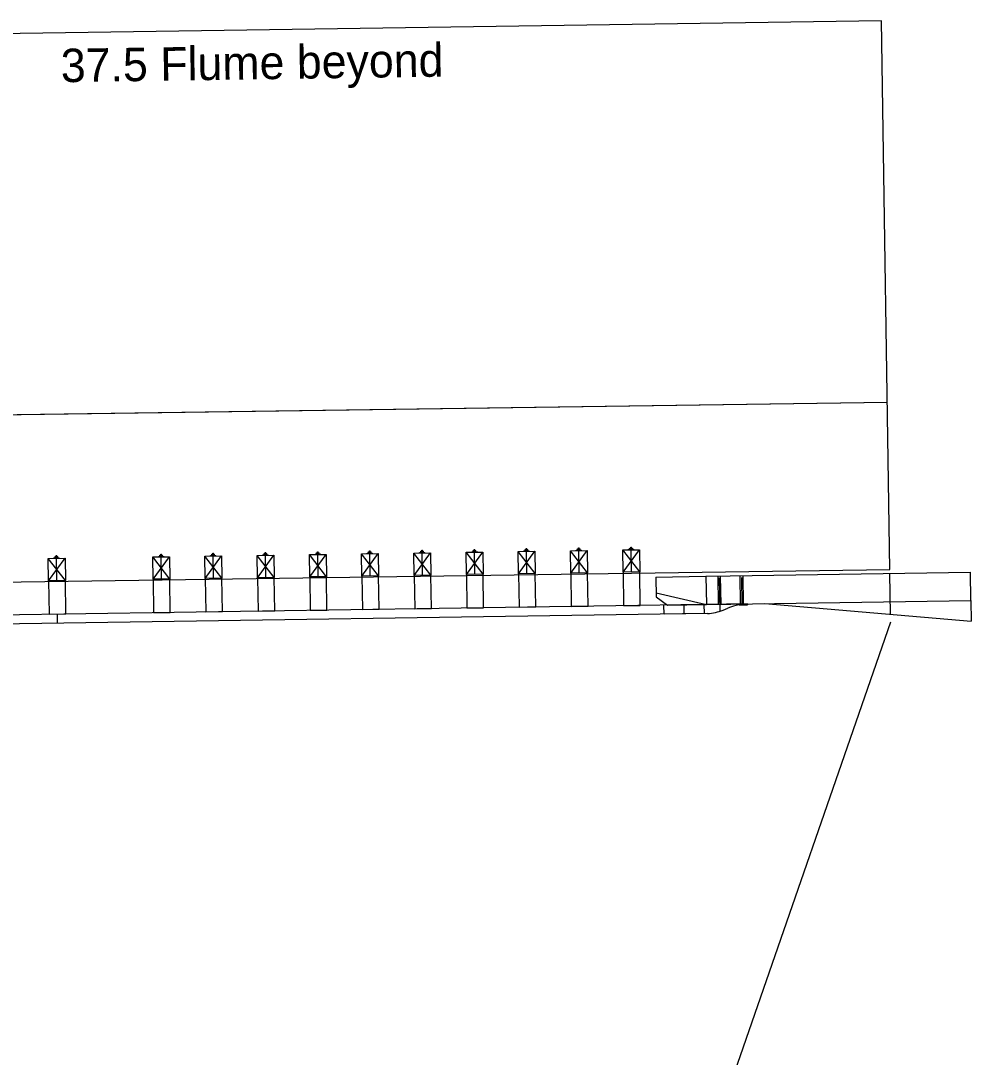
# Model space of a CAD drawing. Extents: x 17498307 to 17498862, y 7167523 to 7167641.
# Drawn here: x 17498465.8 to 17498494.24, y 7167590.21 to 7167621.22 of the extents above; entities that cross this region are included whole.
import ezdxf

# ---------------------------------------------------------------- set-up
doc = ezdxf.new("R2010")
doc.units = 0
for name, color, linetype in [('_CIVIL_CONSTRUCTION', 7, 'Continuous'), ('BridgeSuperStructure', 7, 'Continuous'), ('Draft_DNC', 7, 'Continuous'), ('dsnCellElements', 7, 'Continuous'), ('TL_ForeSlopeBarnRoof', 7, 'Continuous')]:
    doc.layers.add(name, color=color, linetype=linetype)

msp = doc.modelspace()

# ---------------------------------------------------------------- linework, layer by layer
at = {"layer": '_CIVIL_CONSTRUCTION'}
for p, q in [((17498432.532, 7167603.967), (17498491.798, 7167604.808)), ((17498491.825, 7167603.225), (17498476.465, 7167558.992))]:
    msp.add_line(p, q, dxfattribs=at)
at = {"layer": 'BridgeSuperStructure'}
msp.add_line((17498494.238, 7167603.261), (17498494.237, 7167603.261), dxfattribs=at)
at = {"layer": 'Draft_DNC'}
for p, q in [((17498491.553, 7167621.223), (17498454.056, 7167620.664)), ((17498491.798, 7167604.808), (17498491.553, 7167621.223)), ((17498432.461, 7167608.967), (17498491.727, 7167609.807))]:
    msp.add_line(p, q, dxfattribs=at)
at = {"layer": 'dsnCellElements'}
for p, q in [((17498474.674, 7167605.306), (17498474.674, 7167605.335)), ((17498474.674, 7167605.335), (17498474.694, 7167605.335)), ((17498474.694, 7167605.306), (17498474.694, 7167605.335)), ((17498476.236, 7167605.358), (17498476.256, 7167605.359)), ((17498476.237, 7167605.329), (17498476.236, 7167605.358)), ((17498476.257, 7167605.329), (17498476.256, 7167605.359)), ((17498477.769, 7167605.352), (17498477.849, 7167605.353)), ((17498477.769, 7167605.315), (17498477.769, 7167605.352)), ((17498477.785, 7167605.315), (17498477.785, 7167605.352)), ((17498477.799, 7167605.352), (17498477.798, 7167605.382)), ((17498477.798, 7167605.382), (17498477.818, 7167605.382)), ((17498477.819, 7167605.353), (17498477.818, 7167605.382)), ((17498477.833, 7167605.315), (17498477.833, 7167605.353)), ((17498477.849, 7167605.316), (17498477.849, 7167605.353)), ((17498479.292, 7167605.337), (17498479.452, 7167605.34)), ((17498479.292, 7167605.321), (17498479.292, 7167605.337)), ((17498479.331, 7167605.375), (17498479.411, 7167605.376)), ((17498479.332, 7167605.338), (17498479.331, 7167605.375)), ((17498479.348, 7167605.338), (17498479.347, 7167605.375)), ((17498479.361, 7167605.376), (17498479.361, 7167605.405)), ((17498479.361, 7167605.405), (17498479.381, 7167605.405)), ((17498479.381, 7167605.376), (17498479.381, 7167605.405)), ((17498479.396, 7167605.339), (17498479.395, 7167605.376)), ((17498479.412, 7167605.339), (17498479.411, 7167605.376)), ((17498479.452, 7167605.323), (17498479.452, 7167605.34)), ((17498480.684, 7167605.341), (17498481.184, 7167605.349)), ((17498481.194, 7167604.682), (17498480.684, 7167605.341)), ((17498480.694, 7167604.675), (17498481.184, 7167605.349)), ((17498480.854, 7167605.361), (17498481.014, 7167605.363)), ((17498480.854, 7167605.344), (17498480.854, 7167605.361)), ((17498480.893, 7167605.399), (17498480.973, 7167605.4)), ((17498480.894, 7167605.361), (17498480.893, 7167605.399)), ((17498480.91, 7167605.361), (17498480.909, 7167605.399)), ((17498480.923, 7167605.428), (17498480.943, 7167605.429)), ((17498480.923, 7167605.399), (17498480.923, 7167605.428)), ((17498480.944, 7167604.679), (17498480.934, 7167605.345)), ((17498480.943, 7167605.399), (17498480.943, 7167605.429)), ((17498480.958, 7167605.362), (17498480.957, 7167605.4)), ((17498480.974, 7167605.362), (17498480.973, 7167605.4)), ((17498481.014, 7167605.346), (17498481.014, 7167605.363)), ((17498482.247, 7167605.365), (17498482.747, 7167605.372)), ((17498482.757, 7167604.706), (17498482.247, 7167605.365)), ((17498482.257, 7167604.698), (17498482.747, 7167605.372)), ((17498482.416, 7167605.384), (17498482.576, 7167605.386)), ((17498482.417, 7167605.367), (17498482.416, 7167605.384)), ((17498482.456, 7167605.422), (17498482.536, 7167605.423)), ((17498482.456, 7167605.384), (17498482.456, 7167605.422)), ((17498482.472, 7167605.385), (17498482.472, 7167605.422)), ((17498482.486, 7167605.422), (17498482.485, 7167605.452)), ((17498482.485, 7167605.452), (17498482.505, 7167605.452)), ((17498482.507, 7167604.702), (17498482.497, 7167605.369)), ((17498482.506, 7167605.423), (17498482.505, 7167605.452)), ((17498482.52, 7167605.385), (17498482.52, 7167605.423)), ((17498482.536, 7167605.386), (17498482.536, 7167605.423)), ((17498482.577, 7167605.37), (17498482.576, 7167605.386)), ((17498483.809, 7167605.388), (17498484.309, 7167605.396)), ((17498484.319, 7167604.729), (17498483.809, 7167605.388)), ((17498483.819, 7167604.722), (17498484.309, 7167605.396)), ((17498483.979, 7167605.407), (17498484.139, 7167605.41)), ((17498483.979, 7167605.391), (17498483.979, 7167605.407)), ((17498484.018, 7167605.445), (17498484.098, 7167605.446)), ((17498484.019, 7167605.408), (17498484.018, 7167605.445)), ((17498484.035, 7167605.408), (17498484.034, 7167605.445)), ((17498484.048, 7167605.446), (17498484.048, 7167605.475)), ((17498484.048, 7167605.475), (17498484.068, 7167605.475)), ((17498484.069, 7167604.725), (17498484.059, 7167605.392)), ((17498484.068, 7167605.446), (17498484.068, 7167605.475)), ((17498484.083, 7167605.409), (17498484.082, 7167605.446)), ((17498484.099, 7167605.409), (17498484.098, 7167605.446)), ((17498484.139, 7167605.393), (17498484.139, 7167605.41)), ((17498466.623, 7167605.132), (17498467.123, 7167605.139)), ((17498467.133, 7167604.473), (17498466.623, 7167605.132)), ((17498466.633, 7167604.465), (17498467.123, 7167605.139)), ((17498466.793, 7167605.151), (17498466.953, 7167605.153)), ((17498466.793, 7167605.134), (17498466.793, 7167605.151)), ((17498466.833, 7167605.189), (17498466.913, 7167605.19)), ((17498466.833, 7167605.151), (17498466.833, 7167605.189)), ((17498466.849, 7167605.151), (17498466.849, 7167605.189)), ((17498466.863, 7167605.189), (17498466.862, 7167605.219)), ((17498466.862, 7167605.219), (17498466.882, 7167605.219)), ((17498466.883, 7167604.469), (17498466.873, 7167605.135)), ((17498466.883, 7167605.189), (17498466.882, 7167605.219)), ((17498466.897, 7167605.152), (17498466.897, 7167605.19)), ((17498466.913, 7167605.152), (17498466.913, 7167605.19)), ((17498466.953, 7167605.137), (17498466.953, 7167605.153)), ((17498469.748, 7167605.178), (17498470.248, 7167605.186)), ((17498470.258, 7167604.519), (17498469.748, 7167605.178)), ((17498469.758, 7167604.512), (17498470.248, 7167605.186)), ((17498469.918, 7167605.197), (17498470.078, 7167605.2)), ((17498469.918, 7167605.181), (17498469.918, 7167605.197)), ((17498469.957, 7167605.235), (17498470.037, 7167605.236)), ((17498469.958, 7167605.198), (17498469.957, 7167605.235)), ((17498469.974, 7167605.198), (17498469.973, 7167605.236)), ((17498469.987, 7167605.236), (17498469.987, 7167605.265)), ((17498469.987, 7167605.265), (17498470.007, 7167605.265)), ((17498470.008, 7167604.515), (17498469.998, 7167605.182)), ((17498470.007, 7167605.236), (17498470.007, 7167605.265)), ((17498470.022, 7167605.199), (17498470.021, 7167605.236)), ((17498470.038, 7167605.199), (17498470.037, 7167605.236)), ((17498470.078, 7167605.183), (17498470.078, 7167605.2)), ((17498471.31, 7167605.202), (17498471.81, 7167605.209)), ((17498471.82, 7167604.542), (17498471.31, 7167605.202)), ((17498471.32, 7167604.535), (17498471.81, 7167605.209)), ((17498471.48, 7167605.221), (17498471.64, 7167605.223)), ((17498471.48, 7167605.204), (17498471.48, 7167605.221)), ((17498471.52, 7167605.259), (17498471.6, 7167605.26)), ((17498471.52, 7167605.221), (17498471.52, 7167605.259)), ((17498471.536, 7167605.221), (17498471.536, 7167605.259)), ((17498471.55, 7167605.259), (17498471.549, 7167605.289)), ((17498471.549, 7167605.289), (17498471.569, 7167605.289)), ((17498471.57, 7167604.539), (17498471.56, 7167605.205)), ((17498471.57, 7167605.259), (17498471.569, 7167605.289)), ((17498471.584, 7167605.222), (17498471.584, 7167605.26)), ((17498471.6, 7167605.222), (17498471.6, 7167605.26)), ((17498471.64, 7167605.206), (17498471.64, 7167605.223)), ((17498472.873, 7167605.225), (17498473.373, 7167605.232)), ((17498473.383, 7167604.566), (17498472.873, 7167605.225)), ((17498472.883, 7167604.558), (17498473.373, 7167605.232)), ((17498473.042, 7167605.244), (17498473.202, 7167605.246)), ((17498473.043, 7167605.227), (17498473.042, 7167605.244)), ((17498473.082, 7167605.282), (17498473.162, 7167605.283)), ((17498473.082, 7167605.245), (17498473.082, 7167605.282)), ((17498473.098, 7167605.245), (17498473.098, 7167605.282)), ((17498473.112, 7167605.282), (17498473.111, 7167605.312)), ((17498473.111, 7167605.312), (17498473.131, 7167605.312)), ((17498473.133, 7167604.562), (17498473.123, 7167605.229)), ((17498473.132, 7167605.283), (17498473.131, 7167605.312)), ((17498473.146, 7167605.246), (17498473.146, 7167605.283)), ((17498473.162, 7167605.246), (17498473.162, 7167605.283)), ((17498473.203, 7167605.23), (17498473.202, 7167605.246)), ((17498474.435, 7167605.248), (17498474.935, 7167605.256)), ((17498474.945, 7167604.589), (17498474.435, 7167605.248)), ((17498474.445, 7167604.582), (17498474.935, 7167605.256)), ((17498474.605, 7167605.267), (17498474.765, 7167605.27)), ((17498474.605, 7167605.251), (17498474.605, 7167605.267)), ((17498474.644, 7167605.305), (17498474.724, 7167605.306)), ((17498474.645, 7167605.268), (17498474.644, 7167605.305)), ((17498474.661, 7167605.268), (17498474.66, 7167605.306)), ((17498474.695, 7167604.585), (17498474.685, 7167605.252)), ((17498474.709, 7167605.269), (17498474.708, 7167605.306)), ((17498474.725, 7167605.269), (17498474.724, 7167605.306)), ((17498474.765, 7167605.253), (17498474.765, 7167605.27)), ((17498475.997, 7167605.272), (17498476.497, 7167605.279)), ((17498476.507, 7167604.612), (17498475.997, 7167605.272)), ((17498476.007, 7167604.605), (17498476.497, 7167605.279)), ((17498476.167, 7167605.291), (17498476.327, 7167605.293)), ((17498476.167, 7167605.274), (17498476.167, 7167605.291)), ((17498476.207, 7167605.329), (17498476.287, 7167605.33)), ((17498476.207, 7167605.291), (17498476.207, 7167605.329)), ((17498476.223, 7167605.291), (17498476.223, 7167605.329)), ((17498476.257, 7167604.609), (17498476.247, 7167605.275)), ((17498476.271, 7167605.292), (17498476.271, 7167605.33)), ((17498476.287, 7167605.292), (17498476.287, 7167605.33)), ((17498476.327, 7167605.276), (17498476.327, 7167605.293)), ((17498477.56, 7167605.295), (17498478.06, 7167605.302)), ((17498478.07, 7167604.636), (17498477.56, 7167605.295)), ((17498477.57, 7167604.628), (17498478.06, 7167605.302)), ((17498477.729, 7167605.314), (17498477.889, 7167605.316)), ((17498477.73, 7167605.297), (17498477.729, 7167605.314)), ((17498477.82, 7167604.632), (17498477.81, 7167605.299)), ((17498477.89, 7167605.3), (17498477.889, 7167605.316)), ((17498479.122, 7167605.318), (17498479.622, 7167605.326)), ((17498479.632, 7167604.659), (17498479.122, 7167605.318)), ((17498479.132, 7167604.652), (17498479.622, 7167605.326)), ((17498479.382, 7167604.655), (17498479.372, 7167605.322)), ((17498484.319, 7167604.729), (17498483.819, 7167604.722)), ((17498483.819, 7167604.722), (17498483.834, 7167603.722)), ((17498484.334, 7167603.73), (17498484.319, 7167604.729)), ((17498487.029, 7167604.612), (17498494.216, 7167604.719)), ((17498494.229, 7167603.875), (17498494.216, 7167604.719)), ((17498467.133, 7167604.473), (17498466.633, 7167604.465)), ((17498466.633, 7167604.465), (17498466.648, 7167603.466)), ((17498467.148, 7167603.473), (17498467.133, 7167604.473)), ((17498470.258, 7167604.519), (17498469.758, 7167604.512)), ((17498469.758, 7167604.512), (17498469.773, 7167603.512)), ((17498470.273, 7167603.52), (17498470.258, 7167604.519)), ((17498471.82, 7167604.542), (17498471.32, 7167604.535)), ((17498471.32, 7167604.535), (17498471.335, 7167603.536)), ((17498471.835, 7167603.543), (17498471.82, 7167604.542)), ((17498473.382, 7167604.566), (17498472.883, 7167604.558)), ((17498473.382, 7167604.566), (17498472.883, 7167604.558)), ((17498472.883, 7167604.558), (17498472.898, 7167603.559)), ((17498472.883, 7167604.558), (17498472.898, 7167603.559)), ((17498473.397, 7167603.566), (17498473.382, 7167604.566)), ((17498473.397, 7167603.566), (17498473.382, 7167604.566)), ((17498474.945, 7167604.589), (17498474.445, 7167604.582)), ((17498474.445, 7167604.582), (17498474.46, 7167603.582)), ((17498474.96, 7167603.59), (17498474.945, 7167604.589)), ((17498476.507, 7167604.612), (17498476.007, 7167604.605)), ((17498476.007, 7167604.605), (17498476.022, 7167603.606)), ((17498476.522, 7167603.613), (17498476.507, 7167604.612)), ((17498478.069, 7167604.636), (17498477.57, 7167604.628)), ((17498477.57, 7167604.628), (17498477.585, 7167603.629)), ((17498478.084, 7167603.636), (17498478.069, 7167604.636)), ((17498479.632, 7167604.659), (17498479.132, 7167604.652)), ((17498479.132, 7167604.652), (17498479.147, 7167603.652)), ((17498479.647, 7167603.66), (17498479.632, 7167604.659)), ((17498481.194, 7167604.682), (17498480.694, 7167604.675)), ((17498480.694, 7167604.675), (17498480.709, 7167603.676)), ((17498481.209, 7167603.683), (17498481.194, 7167604.682)), ((17498482.756, 7167604.706), (17498482.257, 7167604.698)), ((17498482.257, 7167604.698), (17498482.272, 7167603.699)), ((17498482.771, 7167603.706), (17498482.756, 7167604.706)), ((17498484.8, 7167604.579), (17498486.3, 7167604.601)), ((17498484.8, 7167604.579), (17498484.809, 7167603.985)), ((17498486.3, 7167604.601), (17498487.029, 7167604.612)), ((17498486.3, 7167604.601), (17498486.313, 7167603.757)), ((17498486.654, 7167604.606), (17498486.667, 7167603.763)), ((17498486.697, 7167604.555), (17498486.712, 7167603.552)), ((17498486.75, 7167603.764), (17498486.738, 7167604.608)), ((17498487.333, 7167603.772), (17498487.321, 7167604.616)), ((17498487.363, 7167604.565), (17498487.376, 7167603.747)), ((17498487.404, 7167604.618), (17498487.417, 7167603.774)), ((17498491.818, 7167603.466), (17498491.8, 7167604.683)), ((17498484.807, 7167604.11), (17498486.313, 7167603.757)), ((17498484.809, 7167603.985), (17498485.146, 7167603.74)), ((17498487.042, 7167603.768), (17498494.229, 7167603.875)), ((17498488.063, 7167603.783), (17498494.238, 7167603.261)), ((17498494.229, 7167603.875), (17498494.238, 7167603.261)), ((17498486.25, 7167603.756), (17498460.649, 7167603.375)), ((17498486.254, 7167603.485), (17498460.653, 7167603.104)), ((17498466.648, 7167603.466), (17498467.148, 7167603.473)), ((17498469.773, 7167603.512), (17498470.273, 7167603.52)), ((17498471.335, 7167603.536), (17498471.835, 7167603.543)), ((17498472.898, 7167603.559), (17498473.397, 7167603.566)), ((17498472.898, 7167603.559), (17498473.397, 7167603.566)), ((17498474.46, 7167603.582), (17498474.96, 7167603.59)), ((17498476.022, 7167603.606), (17498476.522, 7167603.613)), ((17498477.585, 7167603.629), (17498478.084, 7167603.636)), ((17498479.147, 7167603.652), (17498479.647, 7167603.66)), ((17498480.709, 7167603.676), (17498481.209, 7167603.683)), ((17498482.272, 7167603.699), (17498482.771, 7167603.706)), ((17498483.834, 7167603.722), (17498484.334, 7167603.73)), ((17498487.542, 7167603.776), (17498485.042, 7167603.738)), ((17498486.045, 7167603.753), (17498485.042, 7167603.738)), ((17498485.046, 7167603.467), (17498485.042, 7167603.738)), ((17498486.35, 7167603.487), (17498485.046, 7167603.467)), ((17498485.146, 7167603.74), (17498486.313, 7167603.757)), ((17498485.65, 7167603.476), (17498485.646, 7167603.747)), ((17498486.254, 7167603.485), (17498486.25, 7167603.756)), ((17498486.313, 7167603.757), (17498487.042, 7167603.768)), ((17498486.811, 7167603.587), (17498486.953, 7167603.645)), ((17498487.292, 7167603.746), (17498487.542, 7167603.75)), ((17498487.542, 7167603.776), (17498487.542, 7167603.75)), ((17498466.902, 7167603.197), (17498466.898, 7167603.468))]:
    msp.add_line(p, q, dxfattribs=at)
for points in [[(17498481.194, 7167604.682), (17498480.694, 7167604.675), (17498480.684, 7167605.341), (17498481.184, 7167605.349)], [(17498482.757, 7167604.706), (17498482.257, 7167604.698), (17498482.247, 7167605.365), (17498482.747, 7167605.372)], [(17498484.319, 7167604.729), (17498483.819, 7167604.722), (17498483.809, 7167605.388), (17498484.309, 7167605.396)], [(17498467.133, 7167604.473), (17498466.633, 7167604.465), (17498466.623, 7167605.132), (17498467.123, 7167605.139)], [(17498470.258, 7167604.519), (17498469.758, 7167604.512), (17498469.748, 7167605.178), (17498470.248, 7167605.186)], [(17498471.82, 7167604.542), (17498471.32, 7167604.535), (17498471.31, 7167605.202), (17498471.81, 7167605.209)], [(17498473.383, 7167604.566), (17498472.883, 7167604.558), (17498472.873, 7167605.225), (17498473.373, 7167605.232)], [(17498474.945, 7167604.589), (17498474.445, 7167604.582), (17498474.435, 7167605.248), (17498474.935, 7167605.256)], [(17498476.507, 7167604.612), (17498476.007, 7167604.605), (17498475.997, 7167605.272), (17498476.497, 7167605.279)], [(17498478.07, 7167604.636), (17498477.57, 7167604.628), (17498477.56, 7167605.295), (17498478.06, 7167605.302)], [(17498479.632, 7167604.659), (17498479.132, 7167604.652), (17498479.122, 7167605.318), (17498479.622, 7167605.326)]]:
    msp.add_lwpolyline(points, close=True, dxfattribs=at)
for centre, major_axis, start_param, end_param in [((17498486.249, 7167604.98), (1.541, 0.023), 4.763574, 5.071137), ((17498487.524, 7167602.426), (-1.379, -0.021), 4.866664, 5.124351)]:
    msp.add_ellipse(centre, major_axis=major_axis, ratio=0.97085, start_param=start_param, end_param=end_param, dxfattribs=at)
at = {"layer": 'TL_ForeSlopeBarnRoof'}
msp.add_lwpolyline([(17498364.726, 7167609.85), (17498384.922, 7167610.151), (17498432.461, 7167608.967), (17498440.339, 7167609.079), (17498491.727, 7167609.807)], dxfattribs=at)

# ---------------------------------------------------------------- texts
at = {"layer": 'Draft_DNC'}
msp.add_text('37.5 Flume beyond', height=1, rotation=0.8552, dxfattribs=at).set_placement((17498467.005, 7167619.382))

doc.saveas('drawing.dxf')
